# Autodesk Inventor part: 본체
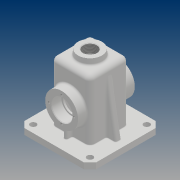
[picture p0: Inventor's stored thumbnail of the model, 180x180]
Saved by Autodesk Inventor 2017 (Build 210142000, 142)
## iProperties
Part Number: 본체
Material: 일반
Document SubType Name: Modeling
Designer: 20
Density: 1 g/cm^3
Appearance: 기본값
Mass: 293.223 g
Surface Area: 897.811 cm^2
Volume: 293.223 cm^3
Author: 20
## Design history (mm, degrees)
sketch "스케치1"
  geometry: L1 (-32.5, 32.5)-(32.5, 32.5); L2 (32.5, 32.5)-(32.5, -32.5); L3 (32.5, -32.5)-(-32.5, -32.5); L4 (-32.5, -32.5)-(-32.5, 32.5); L5 (-32.5, 32.5)-(32.5, -32.5); L6 (32.5, 32.5)-(-32.5, -32.5); 1 further point
  constraints: 12 end point, 2 midpoint, 2 parallel, 1 horizontal, 1 perpendicular
  dimensions: "d0" = 65 distance of L1.start L1.end; "d1" = 65 distance of L1.end L2.end
extrude "돌출1" new body sketch "스케치1" stored distance "d2" = 110; taper "d3" = 0 deg
fillet "모깎기1" dims "d4" = 8
fillet "모깎기2" dims "d5" = 8
feature "쉘1" dims "d6" = 5
sketch "스케치2"
  geometry: L1 (60, -60)-(-60, -60); L2 (-60, -60)-(-60, 60); L3 (-60, 60)-(60, 60); L4 (60, 60)-(60, -60); L5 (60, -60)-(-60, 60); L6 (-60, -60)-(60, 60); 1 further point
  constraints: 12 end point, 2 midpoint, 2 parallel, 1 horizontal, 1 perpendicular
  dimensions: "d7" = 120 distance of L1.start L1.end; "d8" = 120 distance of L1.end L2.end
extrude "돌출2" join sketch "스케치2" distance "d9" = 10; taper "d10" = 0 deg
sketch "스케치3"
  geometry: L1 (-27.5, -27.5)-(27.5, -27.5); L2 (27.5, -27.5)-(27.5, 27.5); L3 (27.5, 27.5)-(-27.5, 27.5); L4 (-27.5, 27.5)-(-27.5, -27.5); L5 (-27.5, -27.5)-(27.5, 27.5); L6 (27.5, -27.5)-(-27.5, 27.5); 1 further point
  constraints: 12 end point, 2 midpoint, 2 parallel, 1 horizontal, 1 perpendicular
  dimensions: "d11" = 55 distance of L2.end L3.end; "d12" = 55 distance of L3.end L1.start
extrude "돌출3" cut sketch "스케치3" distance "d13" = 10; taper "d14" = 0 deg
node "작업 평면1"
sketch "스케치4"
  geometry: C1 r 20 at (0, 0); 1 further point
  constraints: 1 centre point, 1 coincident
  dimensions: "d16" = 40 diameter of C1
extrude "돌출4" join sketch "스케치4" stored distance "d17" = 10; taper "d18" = 5 deg
hole "구멍1" diameter "d21" = 22.835; stored, may be unused: countersink angle "d25" = 90 deg, drill point angle "d27" = 118 deg; dims "d19" = 10, "d20" = 10, "d22" = 50, "d23" = 4, "d24" = 2, "d26" = 59.3
sketch "스케치5"
  geometry: L1 (84.5, -102)-(-35.5, -102) reference; C1 r 27.5 at (24.5, -47); 1 further point
  constraints: 1 centre point, 1 coincident
  dimensions: "d30" = 55 diameter of C1
extrude "돌출5" join sketch "스케치5" distance "d31" = 15; taper "d32" = 0 deg
sketch "스케치6" dims "d33" = 42
  geometry: 3 further points
  constraints: 2 vertical alignment, 1 coincident, 2 other
hole "구멍2" sketch "스케치6" at (0, 21) diameter "d34" = 3.242; stored, may be unused: countersink angle "d38" = 90 deg, drill point angle "d40" = 118 deg; dims "d35" = 8, "d36" = 4, "d37" = 2, "d39" = 10
sketch "스케치7"
  geometry: C1 r 17.5 at (0, 0); 1 further point
  constraints: 1 centre point, 1 coincident
  dimensions: "d44" = 35 diameter of C1
extrude "돌출6" cut sketch "스케치7" distance "d45" = 17; taper "d46" = 0 deg
sketch "스케치8"
  geometry: C1 r 15 at (0, 0); 1 further point
  constraints: 1 centre point, 1 coincident
  dimensions: "d47" = 30 diameter of C1
extrude "돌출7" cut sketch "스케치8" stored distance "d48" = 20; taper "d49" = 0 deg
sketch "스케치12"
  geometry: L1 (0, 84)-(0, -84) reference; L2 (-3, -42.5)-(3, -42.5); L3 (-27.5, -27.5)-(27.5, -27.5) reference; L4 (3, -42.5)-(3, -27.5); L5 (3, -27.5)-(-3, -27.5); L6 (-3, -27.5)-(-3, -42.5); 1 further point
  constraints: 8 end point, 2 point on line, 2 vertical
  dimensions: "d79" = 6 distance of L2.start L2.end; "d80" = 15 distance between parallel lines of L2 L3; "d81" = 3 horizontal distance of point (0, 0) L2.end
extrude "돌출10" join sketch "스케치12" stored distance "d82" = 6; taper "d83" = 0 deg; dims "d7" = 120, "d8" = 120, "d93" = 3
sketch "스케치10"
  geometry: L1 (-60, -45)-(60, -45) reference; L2 (-48, -45)-(-43.473, -19.328); L3 (-60, -55)-(-60, -45) reference; 1 further point
  constraints: 2 end point, 1 point on line
  dimensions: "d53" = 10 deg angle of L2 L3; "d54" = 12 distance from line of L2.start L3; "d55" = 25.67161 vertical distance of L2.start L2.end
feature "리브1" sketch "스케치10" dims "d56" = 1, "d57" = 10, "d58" = 0, "d59" = 0, "d60" = 1, "d61" = 1
chamfer "모따기3" distance "d105" = 10; stored, may be unused: second distance "d106" = 2, angle "d107" = 45 deg
sketch "스케치11"
  geometry: C1 r 5 at (-47.5, 47.5); C2 r 5 at (47.5, 47.5); C3 r 5 at (47.5, -47.5); C4 r 5 at (-47.5, -47.5); 1 further point
  constraints: 4 centre point, 2 horizontal alignment, 2 vertical alignment
  dimensions: "d65" = 10 diameter of C1; "d66" = 10 diameter of C2; "d67" = 10 diameter of C3; "d68" = 10 diameter of C4; "d69" = 95 distance of C4.centre C1.centre; "d70" = 95 distance of C2.centre C1.centre; "d71" = 47.5 horizontal distance of point (0, 0) C1.centre; "d72" = 47.5 horizontal distance of point (0, 0) C2.centre
extrude "돌출9" cut sketch "스케치11" stored distance "d73" = 6; taper "d74" = 0 deg
fillet "모깎기3" dims "d75" = 3
fillet "모깎기4" dims "d76" = 3
fillet "모깎기7" dims "d84" = 3
fillet "모깎기8" dims "d85" = 3
chamfer "모따기2" distance "d86" = 1; stored, may be unused: second distance "d87" = 2, angle "d88" = 45 deg
fillet "모깎기9" dims "d89" = 0.3
fillet "모깎기10" dims "d90" = 3
fillet "모깎기11" dims "d91" = 3
fillet "모깎기12" dims "d92" = 3
fillet "모깎기13" dims "d93" = 3
fillet "모깎기14" dims "d94" = 1
node "작업 평면3"
sketch "스케치14"
  geometry: L1 (57, 0)-(57, 91) reference; L2 (44.5, -18)-(4.5, -18) reference; 2 further points
  constraints: 1 other
  dimensions: "d101" = 32.5 distance from line of L1 point (24.5, 8); "d102" = 26 distance from line of L2 point (24.5, 8)
feature "엠보싱2" sketch "스케치14" dims "d103" = 0.5, "d104" = 0
node "솔리드1"
pattern_circular "원형 패턴1" dims angle "d42" = 360 deg
mirror "미러1"
mirror "미러4"
mirror "미러3"
